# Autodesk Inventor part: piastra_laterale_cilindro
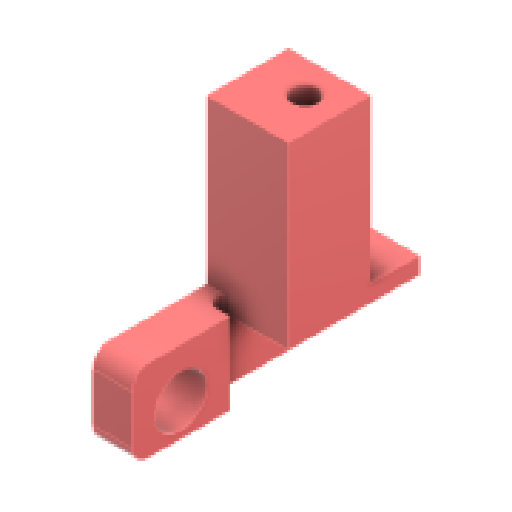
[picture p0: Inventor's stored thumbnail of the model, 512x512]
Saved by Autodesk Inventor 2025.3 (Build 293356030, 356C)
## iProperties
Created: 2025-09
Part Number: piastra_laterale_cilindro
Material: Plastica ABS
Document SubType Name: Modeling
Designer: R5800u
Density: 1.06 g/cm^3
Appearance: Rosso
Author: R5800u
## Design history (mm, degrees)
sketch "Schizzo1"
  geometry: L1 (-2.5, 10)-(2.5, 10); L2 (2.5, 10)-(2.5, -10); L3 (2.5, -10)-(-2.5, -10); L4 (-2.5, -10)-(-2.5, 10); L5 (-2.5, 10)-(2.5, -10); L6 (2.5, 10)-(-2.5, -10); 1 further point
  constraints: 12 end point, 2 midpoint, 2 parallel, 1 horizontal, 1 perpendicular
  dimensions: "d0" = 5 distance of L2.end L3.end; "d1" = 20 distance of L1.end L2.end
extrude "Estrusione1" new body sketch "Schizzo1" stored distance "d2" = 50; taper "d3" = 0 deg
sketch "Schizzo2"
  geometry: L1 (50, 20)-(0, 20) reference; L2 (0, 0)-(25, 0); L3 (25, 0)-(25, 20); L4 (25, 20)-(0, 20); L5 (0, 20)-(0, 0); L6 (30, 1)-(30, 6.7) reference; L7 (25, 0)-(30, 0); L8 (30, 0)-(30, 20); L9 (30, 20)-(25, 20); L10 (25, 20)-(25, 0); 4 further points
  constraints: 16 end point, 4 parallel, 2 horizontal, 2 perpendicular, 1 midpoint, 1 point on line
  dimensions: "d4" = 20 distance of L3.end L2.end
extrude "Estrusione2" join sketch "Schizzo2" distance "d5" = 7; taper "d6" = 0 deg
sketch "Schizzo3"
  geometry: C1 r 4 at (-10, 10) reference; C2 r 8 at (-10, 10); 1 further point
  constraints: 1 centre point, 1 coincident
  dimensions: "d7" = 16 diameter of C2
extrude "Estrusione3" cut sketch "Schizzo3" extent not by distance; stored distance "d8" = 5; taper "d9" = 0 deg
sketch "Schizzo4"
  geometry: L1 (-2.5, -10)-(2.5, -10) reference; L2 (2.5, -10)-(2.5, 10) reference; L3 (2.5, 10)-(-2.5, 10) reference; L4 (-2.5, 10)-(-2.5, -10) reference; 1 further point
extrude "Estrusione4" join sketch "Schizzo4" distance "d10" = 20; taper "d11" = 0 deg
sketch "Schizzo5"
  geometry: L1 (0, 40)-(0, -5) reference; L2 (0, 0)-(20, 0); L3 (20, 0)-(20, 40); L4 (20, 40)-(0, 40); L5 (0, 40)-(0, 0); L6 (7, -5)-(7, -30) reference; L7 (0, 40)-(0, -5) reference; L8 (-5, 40)-(0, 40) reference; L9 (-5, 40)-(-5, -30) reference; L10 (0, 40)-(-5, 40); L11 (-5, -30)-(7, -30) reference; L12 (0, -5)-(7, -5) reference; 5 further points
  constraints: 10 end point, 2 parallel, 2 perpendicular, 1 horizontal, 1 point on line
  dimensions: "d13" = 20 distance of L4.end L3.end; "d14" = 40 distance of L3.end L2.end
extrude "Estrusione5" join sketch "Schizzo5" distance "d15" = 5; taper "d16" = 0 deg
sketch "Schizzo6"
  geometry: L1 (0, 40)-(0, 0) reference; 4 further points; 1 other entity
  constraints: 1 other
  dimensions: "d19" = 10 distance from line of L1 point (10, 15); "d20" = 25 dimension on point (10, 15)
hole "Foro1" sketch "Schizzo6" at (10, 15) diameter "d21" = 4.3; stored, may be unused: countersink angle "d25" = 90 deg, drill point angle "d27" = 118 deg; dims "d22" = 6, "d23" = 8, "d24" = 4.6, "d26" = 8
sketch "Schizzo7"
  geometry: L1 (0, 0)-(0, 20) reference; L2 (0, 10)-(25, 10); 3 further points
  constraints: 2 end point, 1 coincident, 1 horizontal, 1 midpoint, 1 point on line
  dimensions: "d28" = 25 distance of L2.start L2.end; "d29" = 10 distance from line of L1 point (10, 10)
hole "Foro2" sketch "Schizzo7" at (25, 10), (10, 10) diameter "d30" = 4.3; stored, may be unused: countersink angle "d34" = 90 deg, drill point angle "d36" = 118 deg; dims "d31" = 6, "d32" = 4, "d33" = 2, "d35" = 8
sketch "Schizzo8"
  geometry: L1 (-2.5, -10)-(9.5, -10) reference; L2 (9.5, -10)-(9.5, 15) reference; L3 (-2.5, 15)-(9.5, 15) reference; L4 (-2.5, -10)-(-2.5, 15) reference; 1 further point
extrude "Estrusione6" join sketch "Schizzo8" distance "d38" = 5; taper "d39" = 0 deg
fillet "Raccordo4" dims "d40" = 3
sketch "Schizzo9"
  geometry: L1 (0, 0)-(20, 0) reference; L2 (-5, 40)-(-5, -35) reference; L3 (20, 0)-(-5, 0); L4 (-5, 0)-(-5, 25); L5 (-5, 25)-(20, 25); L6 (20, 25)-(20, 0); C1 r 2.15 at (10, 15) reference; 3 further points
  constraints: 8 end point, 2 parallel, 1 horizontal, 1 perpendicular, 1 point on line
  dimensions: "d41" = 25 distance of L3.end L4.end
extrude "Estrusione7" join sketch "Schizzo9" distance "d42" = 50; taper "d43" = 0 deg
fillet "Raccordo5" dims "d44" = 5
sketch "Schizzo10"
  geometry: C1 r 2.15 at (10, 15) reference; 2 further points
  constraints: 1 coincident
hole "Foro3" sketch "Schizzo10" at (10, 15) diameter "d45" = 4.3; stored, may be unused: countersink angle "d49" = 90 deg, drill point angle "d51" = 118 deg; dims "d46" = 6, "d47" = 8, "d48" = 40, "d50" = 8
sketch "Schizzo11"
  geometry: C1 r 8 at (10, 10) reference; C2 r 7 at (10, 10); 1 further point
  constraints: 1 centre point, 1 coincident
  dimensions: "d52" = 14 diameter of C2
extrude "Estrusione8" join sketch "Schizzo11" distance "d53" = 2; taper "d54" = 0 deg
node "Solido1"
node "Riferimento1"
node "Riferimento2"
node "Linea chiusa proiettata1"
node "Linea chiusa proiettata2"
node "Linea chiusa proiettata3"
